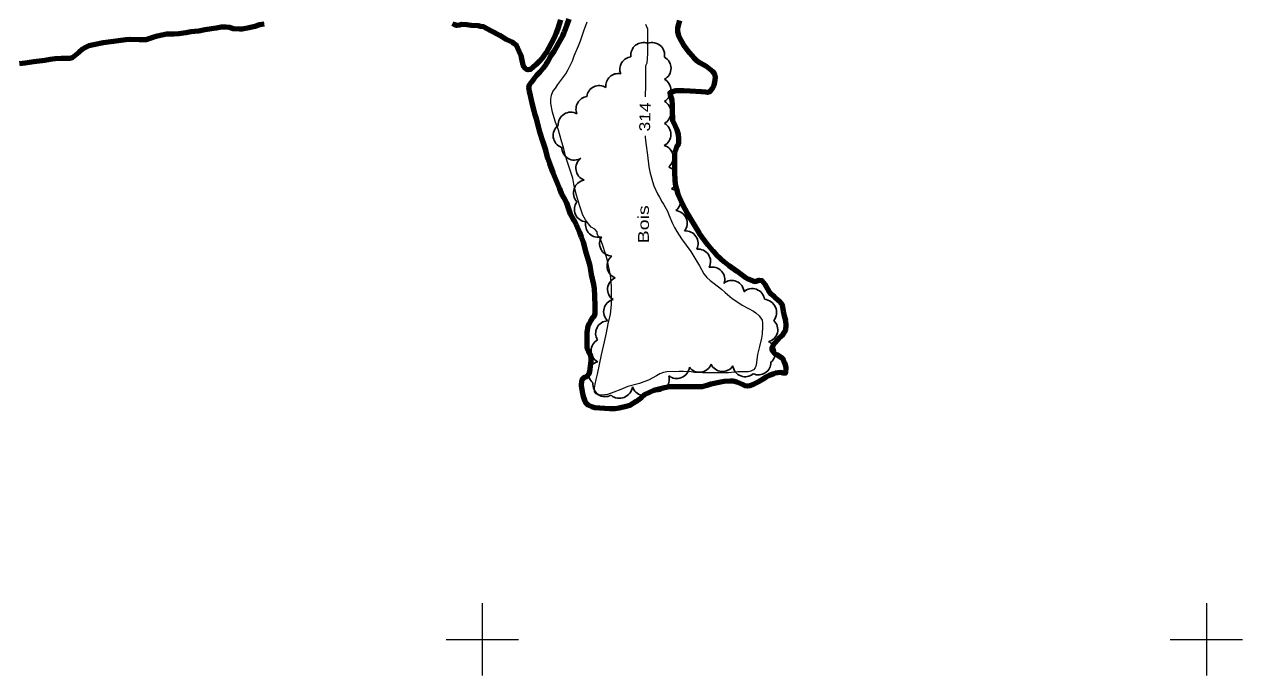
# Model space of a CAD drawing. Extents: x 240591 to 242335, y 5323482 to 5326937.
# Drawn here: x 241473.5 to 241810, y 5323990 to 5324170.1 of the extents above; entities that cross this region are included whole.
import ezdxf

# ---------------------------------------------------------------- set-up
doc = ezdxf.new("R2010")
doc.units = 0
doc.header["$LTSCALE"] = 1.2
doc.linetypes.add('DASH_DOUBLE_DOT', pattern=[9.2, 5, -1.2, 0.3, -1.2, 0.3, -1.2])
doc.linetypes.add('LONG_DASHED', pattern=[7.5, 6, -1.5])
for name, color, linetype, lineweight in [('2', 7, 'Continuous', 13), ('4', 7, 'DASH_DOUBLE_DOT', 53), ('44', 7, 'Continuous', 25), ('61', 7, 'Continuous', 13)]:
    doc.layers.add(name, color=color, linetype=linetype, lineweight=lineweight)

msp = doc.modelspace()

# ---------------------------------------------------------------- linework, layer by layer
at = {"layer": '2'}
for points in [[(241631.1, 5324113.4), (241630.1, 5324114), (241629.3, 5324114.9), (241628.5, 5324116), (241627.8, 5324117.3), (241627.3, 5324118.7), (241626.8, 5324120.1), (241626, 5324122.8), (241625.4, 5324125.3), (241625, 5324127.5), (241624.3, 5324129.7), (241623.4, 5324132.2), (241623, 5324133.7), (241622.5, 5324135.6), (241621.8, 5324138.1), (241621, 5324140.8), (241620.1, 5324143.3), (241619.4, 5324145.8), (241618.9, 5324148.2), (241618.9, 5324149.4), (241619.1, 5324150.5), (241619.5, 5324151.5), (241620.2, 5324152.4), (241620.9, 5324153.4), (241623.1, 5324156.4), (241623.7, 5324157.6), (241624.9, 5324160), (241625.4, 5324161.3), (241626.6, 5324164.1), (241627.1, 5324165.5), (241628, 5324168.3), (241629, 5324170.7)], [(241645.1, 5324170.1), (241645.6, 5324168.8), (241645.6, 5324168.2), (241645.6, 5324165.1), (241645.6, 5324161.9), (241645.4, 5324159.3), (241645.1, 5324158.6), (241645.1, 5324157.9), (241645.1, 5324156.2), (241645.1, 5324153.3), (241645, 5324150)], [(241645, 5324139.2), (241645, 5324138.9), (241645.2, 5324137.2), (241645.6, 5324133.9), (241646, 5324130.7), (241646.3, 5324129.3), (241647, 5324126.6), (241647.4, 5324125.4), (241648.4, 5324123.2), (241648.9, 5324122.3), (241649.5, 5324121.3), (241649.5, 5324121.2)], [(241670.6, 5324074), (241668, 5324073.7), (241667, 5324073.7), (241664.1, 5324073.7), (241660.8, 5324073.7), (241658.6, 5324073.8), (241657.7, 5324074), (241655.6, 5324074.1), (241654.4, 5324074.1), (241651, 5324074), (241650, 5324073.8), (241649, 5324073.4), (241648.1, 5324072.9), (241645.9, 5324071.7), (241644.6, 5324071.2), (241643.4, 5324070.8), (241640.2, 5324069.9), (241638.3, 5324069.1), (241636.3, 5324068.4), (241634.6, 5324067.7), (241633, 5324067.5), (241632.1, 5324067.5), (241631.4, 5324067.9), (241631, 5324068.5), (241631, 5324069.5), (241631.2, 5324070.6), (241631.4, 5324071.9), (241631.8, 5324073.3), (241632.4, 5324076), (241632.9, 5324078.7), (241633.2, 5324079.9), (241633.7, 5324082.3), (241634.3, 5324084.8), (241634.8, 5324087.3), (241635.4, 5324089.9), (241635.7, 5324092.6), (241635.7, 5324093.9), (241635.7, 5324097.6), (241635.5, 5324100), (241635.3, 5324101.1), (241634.6, 5324104.7), (241634.3, 5324105.7), (241633.4, 5324108.6), (241632.8, 5324110.2), (241632.3, 5324111.3), (241631.9, 5324111.7), (241631.7, 5324112.2), (241631.7, 5324112.7), (241631.1, 5324113.4)]]:
    msp.add_lwpolyline(points, dxfattribs=at)
at = {"layer": '2', "linetype": 'LONG_DASHED'}
msp.add_lwpolyline([(241649.5, 5324121.2), (241650, 5324120.3), (241650.4, 5324119.7), (241651.1, 5324118.4), (241651.5, 5324117.4), (241652.5, 5324115), (241653.1, 5324113.9), (241653.7, 5324112.8), (241655, 5324110.8), (241656.3, 5324109), (241657.6, 5324107.3), (241658.7, 5324105.4), (241660, 5324103.3), (241661.2, 5324101.1), (241662, 5324100.1), (241662.9, 5324099.2), (241664, 5324098.4), (241666.1, 5324096.8), (241667.1, 5324095.9), (241669, 5324094.3), (241670, 5324093.6), (241671.8, 5324092.4), (241673.5, 5324091.5), (241674.9, 5324090.8), (241675.5, 5324090.3), (241676.5, 5324089.5), (241677.3, 5324088.3), (241677.4, 5324087.5), (241677.4, 5324086.5), (241677.3, 5324084.4), (241677.1, 5324083.3), (241676.6, 5324081), (241676, 5324078.8), (241675.7, 5324076.7), (241675.6, 5324075.8), (241675.4, 5324075.1), (241674.9, 5324074.5), (241674.2, 5324074.2), (241673.4, 5324074), (241672.5, 5324074), (241670.6, 5324074)], dxfattribs=at)
at = {"layer": '4', "linetype": 'Continuous', "lineweight": 90}
for points in [[(241539.7, 5324170.1), (241538.5, 5324169.9), (241537.2, 5324169.5), (241535.6, 5324169.1), (241533.7, 5324168.7), (241533, 5324168.7), (241531.3, 5324168.8), (241530.2, 5324169.2), (241529.2, 5324169.3), (241527.9, 5324169.3), (241526.5, 5324169), (241523.4, 5324168.5), (241521.6, 5324168.2)], [(241621.6, 5324171.3), (241620.9, 5324168.9), (241620.4, 5324167.6), (241620.1, 5324166.9), (241618.9, 5324164.6), (241617.6, 5324162.2), (241616.9, 5324161.2), (241615.8, 5324159.9), (241614.8, 5324158.9), (241613.3, 5324157.6), (241612.7, 5324157.5), (241612.2, 5324157.6), (241611.7, 5324157.9), (241611.5, 5324158.3), (241611.3, 5324158.8), (241611, 5324160.1), (241610.7, 5324161.4), (241610.2, 5324162.6), (241609.4, 5324164.3), (241608.8, 5324164.7), (241608.4, 5324165), (241606.6, 5324165.9), (241604.8, 5324167), (241602.5, 5324168.2), (241600.3, 5324169.4), (241599.5, 5324169.5), (241598.9, 5324169.6), (241596.9, 5324169.7), (241595.7, 5324169.9), (241594.3, 5324170), (241593.7, 5324169.8), (241593, 5324169.7), (241592.4, 5324169.9), (241591.8, 5324170.2)], [(241627.4, 5324070.2), (241627.5, 5324071.6), (241627.8, 5324072.1), (241628.2, 5324072.5), (241628.9, 5324072.7), (241629.5, 5324073.4), (241629.7, 5324074.1), (241630.1, 5324076.9), (241630.1, 5324078), (241629.9, 5324078.7), (241629.6, 5324079.1), (241629, 5324080.5), (241629, 5324081), (241629, 5324082.1), (241629, 5324084.9), (241629.2, 5324086.7), (241629.5, 5324087.2), (241630, 5324088.1), (241630.6, 5324089.1), (241631, 5324089.5), (241631.2, 5324090.1), (241631.2, 5324090.6), (241631.2, 5324092.1), (241631.1, 5324095), (241631, 5324096.9), (241630.8, 5324098.1), (241630.2, 5324100.9), (241629.8, 5324103.3), (241629.4, 5324104.6), (241628.7, 5324107), (241627.9, 5324109.8), (241627.4, 5324111.2), (241626.9, 5324112.5), (241626.3, 5324114), (241626, 5324114.6), (241625.5, 5324115.7), (241625.1, 5324116.3), (241624.4, 5324117.6), (241623.9, 5324119), (241623.3, 5324120.6), (241622.5, 5324122.2), (241621.9, 5324123.3), (241621.4, 5324124.6), (241620.6, 5324126.6), (241619.6, 5324129), (241618.6, 5324131.5), (241618.1, 5324133), (241617.5, 5324135.3), (241616.7, 5324137.8), (241615.9, 5324140.3), (241615.5, 5324141.8), (241615, 5324143.9), (241614.6, 5324145), (241614.3, 5324146.1), (241613.7, 5324148.6), (241613.3, 5324150.4), (241613, 5324151.6), (241612.8, 5324152.6), (241613.1, 5324153.5), (241613.5, 5324154), (241614.3, 5324155.1), (241615.1, 5324156), (241616, 5324156.9), (241616.8, 5324157.9), (241617.6, 5324159), (241618.2, 5324159.9), (241618.9, 5324161.3), (241619.8, 5324162.6), (241620.6, 5324163.9), (241621.1, 5324164.9), (241622.2, 5324166.9), (241622.6, 5324167.9), (241623.4, 5324170), (241624, 5324171.6)], [(241654.5, 5324171.1), (241653.9, 5324169.1), (241653.9, 5324168.1), (241654.2, 5324166.9), (241654.8, 5324165.7), (241655.6, 5324164.4), (241656.5, 5324163.2), (241657.2, 5324162.2), (241658.4, 5324160.8), (241659.2, 5324160.1), (241660.2, 5324159.4), (241661.8, 5324158.5), (241663.6, 5324157.1), (241664, 5324156.5), (241664.2, 5324156), (241664.3, 5324155.4), (241664.1, 5324154.1), (241663.9, 5324153.1), (241663.5, 5324152.2), (241662.8, 5324151.4), (241662.2, 5324151.2), (241661.6, 5324151.3), (241660.4, 5324151.4), (241657.4, 5324151.6), (241655.7, 5324151.7), (241653.4, 5324151.7), (241651.8, 5324151.1), (241651.9, 5324150.6), (241652.3, 5324149.2), (241652.4, 5324147.7), (241652.4, 5324146.5), (241652.5, 5324143.5), (241652.8, 5324142.9), (241653.7, 5324140.9), (241654.1, 5324139.6), (241654.2, 5324138.5), (241654.2, 5324137), (241653.8, 5324136.5), (241653.5, 5324135.7), (241653.1, 5324134.6)], [(241521.6, 5324168.2), (241519.5, 5324168), (241518.1, 5324167.7), (241516.2, 5324167.4), (241514.8, 5324167.3), (241512.8, 5324167.3), (241511.5, 5324167.1), (241510.2, 5324166.8), (241509, 5324166.4), (241507.1, 5324165.8), (241506.5, 5324165.8), (241505.3, 5324165.8), (241502.7, 5324165.9), (241501.5, 5324165.8), (241499.5, 5324165.5), (241498.1, 5324165.3), (241495.3, 5324164.9), (241492.6, 5324164.4), (241491.3, 5324164.1), (241490.2, 5324163.6), (241489.6, 5324163.2), (241488.6, 5324162.3), (241486.7, 5324160.8), (241486.1, 5324160.6), (241485.4, 5324160.6), (241483.7, 5324160.6), (241482, 5324160.5), (241480.6, 5324160.3), (241479.2, 5324160.1), (241476.1, 5324159.7), (241473.7, 5324159.3), (241472.2, 5324159.1)], [(241653.1, 5324134.6), (241653.1, 5324133.5), (241653.1, 5324131.9), (241653.1, 5324129.3), (241653.2, 5324126.8), (241653.4, 5324125.4), (241653.7, 5324124.2), (241654, 5324123.1), (241654.8, 5324121.3), (241655.2, 5324120.4), (241656.7, 5324117.7), (241657.6, 5324116.1), (241658.6, 5324114.4), (241659.9, 5324112.3), (241660.6, 5324111.3), (241662.3, 5324109.1), (241663.7, 5324107.4), (241664.6, 5324106.4), (241665.9, 5324105.2), (241666.7, 5324104.5), (241668.1, 5324103.4), (241670.3, 5324101.8), (241672.5, 5324100.2), (241673.5, 5324099.6), (241674.7, 5324099.1), (241675.4, 5324099), (241676.5, 5324099.3), (241677.2, 5324099.2), (241677.7, 5324098.7), (241678, 5324098.2), (241679.1, 5324096.3), (241679.8, 5324095.5), (241680.6, 5324094.8), (241681.8, 5324093.7), (241682.7, 5324092.7), (241682.9, 5324092), (241683.1, 5324090.8), (241683.4, 5324089.5), (241683.7, 5324088.2), (241683.8, 5324086.9), (241683.7, 5324085.5), (241683.4, 5324085), (241682.7, 5324083.9), (241681.8, 5324083.1), (241680.6, 5324081.8), (241680, 5324080.6), (241680, 5324080.1), (241680.3, 5324079.5), (241680.7, 5324079.1), (241681.3, 5324078.8), (241682.8, 5324077.8), (241683.2, 5324077.2), (241683.5, 5324076.5), (241683.8, 5324075.3), (241683.7, 5324073.6), (241683.1, 5324073.6), (241682.4, 5324073.8), (241681, 5324073.6), (241680.5, 5324073.4), (241679.2, 5324073), (241678.3, 5324072.5), (241677.4, 5324071.9), (241676.5, 5324071.3), (241675, 5324070.6), (241673.8, 5324070.1), (241673.2, 5324070), (241672.6, 5324070.1), (241672, 5324070.4), (241670.3, 5324071.1), (241669.3, 5324071.4), (241668.5, 5324071.4), (241666.8, 5324071.3), (241665.8, 5324071.1), (241663.1, 5324070.6), (241662, 5324070.2), (241660.7, 5324069.8), (241660.1, 5324069.8), (241658.7, 5324069.8), (241656, 5324069.8), (241653.3, 5324069.8), (241651.6, 5324069.8), (241650.3, 5324069.6), (241647.4, 5324068.8), (241646.2, 5324068.3), (241644.8, 5324067.6), (241644, 5324066.9), (241642.5, 5324065.8), (241640.7, 5324064.7), (241639.7, 5324064.4), (241637.8, 5324063.9), (241636.7, 5324063.8), (241635.2, 5324063.8), (241632.5, 5324063.9), (241631.1, 5324064), (241630.4, 5324064.2), (241629.2, 5324064.8), (241628.8, 5324065.2), (241628.4, 5324065.8), (241628, 5324066.9), (241627.8, 5324067.9), (241627.4, 5324070.2)]]:
    msp.add_lwpolyline(points, dxfattribs=at)
at = {"layer": '44'}
for centre, radius, start, end in [((241648.615, 5324145.725), 3.485, 299.10171, 60.89829), ((241648.587, 5324139.641), 3.494, 298.80851, 60.44008), ((241649.224, 5324133.265), 3.476, 310.46569, 72.48676), ((241650.204, 5324127.375), 3.487, 306.7412, 68.53506), ((241651.218, 5324121.249), 3.499, 310.27896, 72.1572), ((241653.074, 5324115.102), 3.501, 321.64613, 83.34856), ((241656.132, 5324109.464), 3.48, 333.28176, 95.14341), ((241638.084, 5324096.801), 3.482, 113.24563, 235.2583), ((241636.968, 5324090.592), 3.459, 104.53448, 226.33543), ((241677.592, 5324090.392), 3.674, 322.5872, 84.55924), ((241634.723, 5324084.669), 3.424, 92.39259, 212.77488), ((241678.182, 5324085.648), 3.424, 283.77747, 47.17482), ((241633.488, 5324079.812), 3.424, 118.69746, 241.70522), ((241677.54, 5324079.298), 3.428, 309.33292, 64.79596), ((241632.803, 5324073.501), 3.426, 105.88597, 229.22126), ((241653.7, 5324075.657), 3.535, 231.51124, 353.22884), ((241648.21, 5324071.947), 3.422, 254.98577, 15.98767)]:
    msp.add_arc(centre, radius, start, end, dxfattribs=at)
for centre, major_axis, ratio, start_param, end_param in [((241644.471, 5324161.555), (-2.775, -2.061), 0.999863, 3.701531, 5.7881063), ((241646.91, 5324161.565), (-2.695, 2.165), 0.999939, 3.6363848, 5.7417477), ((241641.431, 5324157.631), (-1.282, -3.204), 0.999864, 3.6328158, 5.4669932), ((241648.682, 5324157.899), (2.901, 1.867), 0.999448, 4.6322525, 6.7905745), ((241637.554, 5324153.005), (-0.462, 3.42), 0.999663, 5.9535351, 7.8432519), ((241632.266, 5324149.67), (-3.02, -1.68), 0.99994, 3.6349666, 5.6551206), ((241648.615, 5324151.815), (3.427, -0.638), 0.999887, 5.4044922, 7.5300596), ((241629.31, 5324146.653), (-2.186, -2.662), 0.999865, 3.9443066, 5.7941358), ((241624.433, 5324142.313), (-2.925, -1.851), 0.99994, 3.6356217, 5.7891562), ((241623.026, 5324139.291), (0.488, -3.417), 0.999864, 3.6344287, 5.7903493), ((241625.419, 5324135.974), (2.991, -1.72), 0.999939, 3.6344265, 5.7903513), ((241629.296, 5324130.264), (-1.368, -3.176), 0.999682, 4.1851173, 6.3369585), ((241628.804, 5324123.458), (-3.279, 1.561), 0.999786, 5.3518094, 7.4747707), ((241628.893, 5324118.896), (1.432, -3.149), 0.999758, 3.6351791, 5.7769058), ((241631.959, 5324114.658), (2.429, -2.451), 0.999864, 3.6996625, 5.7906018), ((241635.854, 5324109.468), (-3.13, -1.508), 0.997933, 5.2597656, 7.3874474), ((241637.927, 5324103.257), (-3.423, 0.61), 0.999962, 5.5505575, 7.6727566), ((241659.582, 5324104.458), (-1.939, 2.865), 0.999863, 3.6375667, 5.7872112), ((241663.495, 5324099.507), (-2.335, 2.55), 0.999864, 3.6360369, 5.788741), ((241668.842, 5324095.823), (-3.17, 1.361), 0.999985, 3.6331809, 5.7915968), ((241674.523, 5324093.555), (-3.244, 1.183), 0.999985, 3.6352001, 5.7895782), ((241659.979, 5324077.325), (0.467, -3.435), 0.999733, 5.2224151, 7.3485792), ((241666.339, 5324077.516), (-0.273, -3.436), 0.999978, 5.2247569, 7.3473365), ((241672.602, 5324076.047), (3.195, -1.22), 0.999985, 3.6344239, 5.7903542), ((241676.285, 5324076.566), (2.745, 2.05), 0.999985, 3.6353329, 5.6661828), ((241633.975, 5324070.551), (2.829, -1.937), 0.999984, 3.6380166, 5.7867612), ((241637.847, 5324070.335), (1.356, -3.394), 0.999995, 5.2201211, 7.343749), ((241644.733, 5324070.882), (3.359, -0.641), 0.999985, 3.6336953, 5.7622354)]:
    msp.add_ellipse(centre, major_axis=major_axis, ratio=ratio, start_param=start_param, end_param=end_param, dxfattribs=at)
at = {"layer": '61'}
for points in [[(241600, 5324010), (241600, 5324000), (241600, 5323990)], [(241800, 5324010), (241800, 5324000), (241800, 5323990)], [(241590, 5324000), (241600, 5324000), (241610, 5324000)], [(241790, 5324000), (241800, 5324000), (241810, 5324000)]]:
    msp.add_lwpolyline(points, dxfattribs=at)

# ---------------------------------------------------------------- texts
at = {"layer": '2', "width": 1.2}
msp.add_text('314', height=3, rotation=88.477, dxfattribs=at).set_placement((241646.3, 5324140.4))
at = {"layer": '44', "width": 1.35}
msp.add_text('Bois', height=3, rotation=90, dxfattribs=at).set_placement((241646, 5324109.5))

doc.saveas('drawing.dxf')
